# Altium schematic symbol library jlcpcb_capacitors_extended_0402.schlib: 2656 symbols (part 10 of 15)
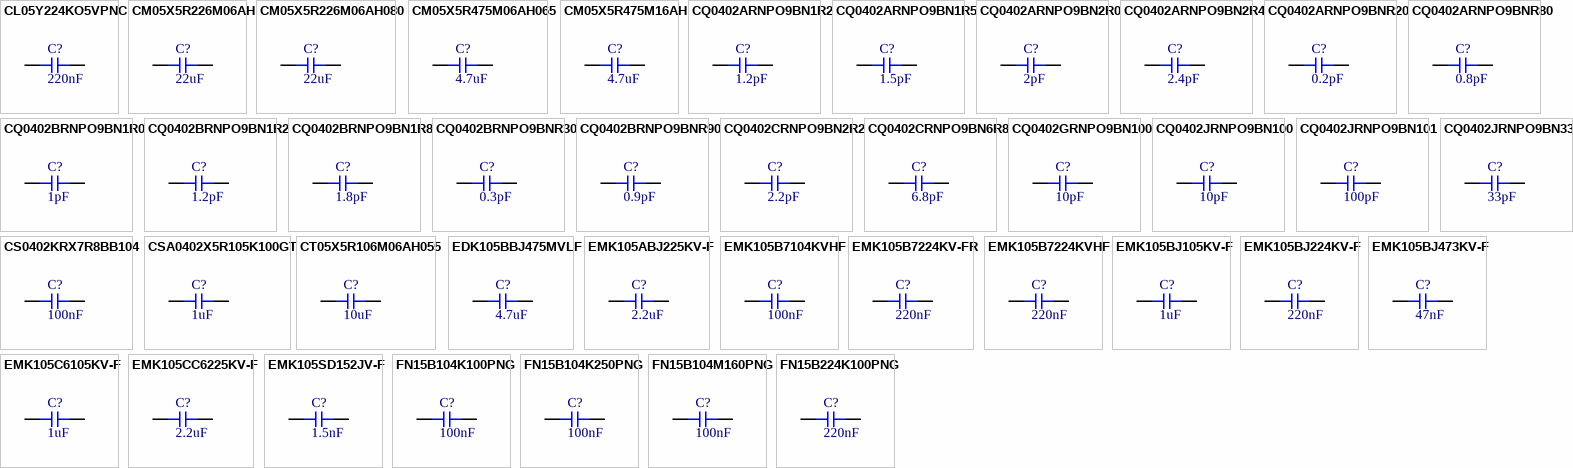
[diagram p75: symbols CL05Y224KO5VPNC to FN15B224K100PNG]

## CQ0402ARNPO9BN2R4
designator C?  Capacitance: 2.4pF  (hidden comment: *)
Capacitor, Ceramic (MLCC), 2.4pF, ±0.05pF, 50V, NP0, ±0.05pF, SMD 0402; Manufacturer: YAGEO; Manufacturer Part Number: CQ0402ARNPO9BN2R4
footprint CAP-0402 (0402 (1005M) Capacitor)
pins: 1, 2

## CQ0402ARNPO9BNR20
designator C?  Capacitance: 0.2pF  (hidden comment: *)
Capacitor, Ceramic (MLCC), 0.2pF, ±0.05pF, 50V, NP0, ±0.05pF, SMD 0402; Manufacturer: YAGEO; Manufacturer Part Number: CQ0402ARNPO9BNR20
footprint CAP-0402 (0402 (1005M) Capacitor)
pins: 1, 2

## CQ0402ARNPO9BNR80
designator C?  Capacitance: 0.8pF  (hidden comment: *)
Capacitor, Ceramic (MLCC), 0.8pF, ±0.05pF, 50V, NP0, ±0.05pF, SMD 0402; Manufacturer: YAGEO; Manufacturer Part Number: CQ0402ARNPO9BNR80
footprint CAP-0402 (0402 (1005M) Capacitor)
pins: 1, 2

## CQ0402BRNPO9BN1R0
designator C?  Capacitance: 1pF  (hidden comment: *)
Capacitor, Ceramic (MLCC), 1pF, ±0.1pF, 50V, NP0, ±0.1pF, SMD 0402; Manufacturer: YAGEO; Manufacturer Part Number: CQ0402BRNPO9BN1R0
footprint CAP-0402 (0402 (1005M) Capacitor)
pins: 1, 2

## CQ0402BRNPO9BN1R2
designator C?  Capacitance: 1.2pF  (hidden comment: *)
Capacitor, Ceramic (MLCC), 1.2pF, ±0.1pF, 50V, NP0, ±0.1pF, SMD 0402; Manufacturer: YAGEO; Manufacturer Part Number: CQ0402BRNPO9BN1R2
footprint CAP-0402 (0402 (1005M) Capacitor)
pins: 1, 2

## CQ0402BRNPO9BN1R8
designator C?  Capacitance: 1.8pF  (hidden comment: *)
Capacitor, Ceramic (MLCC), 1.8pF, ±0.1pF, 50V, NP0, ±0.1pF, SMD 0402; Manufacturer: YAGEO; Manufacturer Part Number: CQ0402BRNPO9BN1R8
footprint CAP-0402 (0402 (1005M) Capacitor)
pins: 1, 2

## CQ0402BRNPO9BNR30
designator C?  Capacitance: 0.3pF  (hidden comment: *)
Capacitor, Ceramic (MLCC), 0.3pF, ±0.1pF, 50V, NP0, ±0.1pF, SMD 0402; Manufacturer: YAGEO; Manufacturer Part Number: CQ0402BRNPO9BNR30
footprint CAP-0402 (0402 (1005M) Capacitor)
pins: 1, 2

## CQ0402BRNPO9BNR90
designator C?  Capacitance: 0.9pF  (hidden comment: *)
Capacitor, Ceramic (MLCC), 0.9pF, ±0.1pF, 50V, NP0, ±0.1pF, SMD 0402; Manufacturer: YAGEO; Manufacturer Part Number: CQ0402BRNPO9BNR90
footprint CAP-0402 (0402 (1005M) Capacitor)
pins: 1, 2

## CQ0402CRNPO9BN2R2
designator C?  Capacitance: 2.2pF  (hidden comment: *)
Capacitor, Ceramic (MLCC), 2.2pF, ±0.25pF, 50V, NP0, ±0.25pF, SMD 0402; Manufacturer: YAGEO; Manufacturer Part Number: CQ0402CRNPO9BN2R2
footprint CAP-0402 (0402 (1005M) Capacitor)
pins: 1, 2

## CQ0402CRNPO9BN6R8
designator C?  Capacitance: 6.8pF  (hidden comment: *)
Capacitor, Ceramic (MLCC), 6.8pF, ±0.25pF, 50V, NP0, ±0.25pF, SMD 0402; Manufacturer: YAGEO; Manufacturer Part Number: CQ0402CRNPO9BN6R8
footprint CAP-0402 (0402 (1005M) Capacitor)
pins: 1, 2

## CQ0402GRNPO9BN100
designator C?  Capacitance: 10pF  (hidden comment: *)
Capacitor, Ceramic (MLCC), 10pF, ±2%, 50V, NP0, ±2%, SMD 0402; Manufacturer: YAGEO; Manufacturer Part Number: CQ0402GRNPO9BN100
footprint CAP-0402 (0402 (1005M) Capacitor)
pins: 1, 2

## CQ0402JRNPO9BN100
designator C?  Capacitance: 10pF  (hidden comment: *)
Capacitor, Ceramic (MLCC), 10pF, ±5%, 50V, NP0, ±5%, SMD 0402; Manufacturer: YAGEO; Manufacturer Part Number: CQ0402JRNPO9BN100
footprint CAP-0402 (0402 (1005M) Capacitor)
pins: 1, 2

## CQ0402JRNPO9BN101
designator C?  Capacitance: 100pF  (hidden comment: *)
Capacitor, Ceramic (MLCC), 100pF, ±5%, 50V, NP0, ±5%, SMD 0402; Manufacturer: YAGEO; Manufacturer Part Number: CQ0402JRNPO9BN101
footprint CAP-0402 (0402 (1005M) Capacitor)
pins: 1, 2

## CQ0402JRNPO9BN330
designator C?  Capacitance: 33pF  (hidden comment: *)
Capacitor, Ceramic (MLCC), 33pF, ±5%, 50V, NP0, ±5%, SMD 0402; Manufacturer: YAGEO; Manufacturer Part Number: CQ0402JRNPO9BN330
footprint CAP-0402 (0402 (1005M) Capacitor)
pins: 1, 2

## CS0402KRX7R8BB104
designator C?  Capacitance: 100nF  (hidden comment: *)
Capacitor, Ceramic (MLCC), 100nF, ±10%, 25V, X7R, ±10%, SMD 0402; Manufacturer: YAGEO; Manufacturer Part Number: CS0402KRX7R8BB104
footprint CAP-0402 (0402 (1005M) Capacitor)
pins: 1, 2

## CSA0402X5R105K100GT
designator C?  Capacitance: 1uF  (hidden comment: *)
Capacitor, Ceramic (MLCC), 1uF, ±10%, 10V, X5R, ±10%, SMD 0402; Manufacturer: HRE; Manufacturer Part Number: CSA0402X5R105K100GT
footprint CAP-0402 (0402 (1005M) Capacitor)
pins: 1, 2

## CT05X5R106M06AH055
designator C?  Capacitance: 10uF  (hidden comment: *)
Capacitor, Ceramic (MLCC), 10uF, ±20%, 6.3V, X5R, ±20%, SMD 0402; Manufacturer: Kyocera; Manufacturer Part Number: CT05X5R106M06AH055
footprint CAP-0402 (0402 (1005M) Capacitor)
pins: 1, 2

## EDK105BBJ475MVLF
designator C?  Capacitance: 4.7uF  (hidden comment: *)
Capacitor, Ceramic (MLCC), 4.7uF, ±20%, 16V, ±20%, SMD 0402; Manufacturer: Taiyo Yuden; Manufacturer Part Number: EDK105BBJ475MVLF
footprint CAP-0402 (0402 (1005M) Capacitor)
pins: 1, 2

## EMK105ABJ225KV-F
designator C?  Capacitance: 2.2uF  (hidden comment: *)
Capacitor, Ceramic (MLCC), 2.2uF, ±10%, 16V, X5R, ±10%, SMD 0402; Manufacturer: Taiyo Yuden; Manufacturer Part Number: EMK105ABJ225KV-F
footprint CAP-0402 (0402 (1005M) Capacitor)
pins: 1, 2

## EMK105B7104KVHF
designator C?  Capacitance: 100nF  (hidden comment: *)
Capacitor, Ceramic (MLCC), 100nF, ±10%, 16V, X7R, ±10%, SMD 0402; Manufacturer: Taiyo Yuden; Manufacturer Part Number: EMK105B7104KVHF
footprint CAP-0402 (0402 (1005M) Capacitor)
pins: 1, 2

## EMK105B7224KV-FR
designator C?  Capacitance: 220nF  (hidden comment: *)
Capacitor, Ceramic (MLCC), 220nF, ±10%, 16V, X7R, ±10%, SMD 0402; Manufacturer: Taiyo Yuden; Manufacturer Part Number: EMK105B7224KV-FR
footprint CAP-0402 (0402 (1005M) Capacitor)
pins: 1, 2

## EMK105B7224KVHF
designator C?  Capacitance: 220nF  (hidden comment: *)
Capacitor, Ceramic (MLCC), 220nF, ±10%, 16V, X7R, ±10%, SMD 0402; Manufacturer: Taiyo Yuden; Manufacturer Part Number: EMK105B7224KVHF
footprint CAP-0402 (0402 (1005M) Capacitor)
pins: 1, 2

## EMK105BJ105KV-F
designator C?  Capacitance: 1uF  (hidden comment: *)
Capacitor, Ceramic (MLCC), 1uF, ±10%, 16V, X5R, ±10%, SMD 0402; Manufacturer: Taiyo Yuden; Manufacturer Part Number: EMK105BJ105KV-F
footprint CAP-0402 (0402 (1005M) Capacitor)
pins: 1, 2

## EMK105BJ224KV-F
designator C?  Capacitance: 220nF  (hidden comment: *)
Capacitor, Ceramic (MLCC), 220nF, ±10%, 16V, X5R, ±10%, SMD 0402; Manufacturer: Taiyo Yuden; Manufacturer Part Number: EMK105BJ224KV-F
footprint CAP-0402 (0402 (1005M) Capacitor)
pins: 1, 2

## EMK105BJ473KV-F
designator C?  Capacitance: 47nF  (hidden comment: *)
Capacitor, Ceramic (MLCC), 47nF, ±10%, 16V, X5R, ±10%, SMD 0402; Manufacturer: Taiyo Yuden; Manufacturer Part Number: EMK105BJ473KV-F
footprint CAP-0402 (0402 (1005M) Capacitor)
pins: 1, 2

## EMK105C6105KV-F
designator C?  Capacitance: 1uF  (hidden comment: *)
Capacitor, Ceramic (MLCC), 1uF, ±10%, 16V, ±10%, SMD 0402; Manufacturer: Taiyo Yuden; Manufacturer Part Number: EMK105C6105KV-F
footprint CAP-0402 (0402 (1005M) Capacitor)
pins: 1, 2

## EMK105CC6225KV-F
designator C?  Capacitance: 2.2uF  (hidden comment: *)
Capacitor, Ceramic (MLCC), 2.2uF, ±10%, ±10%, SMD 0402; Manufacturer: Taiyo Yuden; Manufacturer Part Number: EMK105CC6225KV-F
footprint CAP-0402 (0402 (1005M) Capacitor)
pins: 1, 2

## EMK105SD152JV-F
designator C?  Capacitance: 1.5nF  (hidden comment: *)
Capacitor, Ceramic (MLCC), 1.5nF, ±5%, 16V, ±5%, SMD 0402; Manufacturer: Taiyo Yuden; Manufacturer Part Number: EMK105SD152JV-F
footprint CAP-0402 (0402 (1005M) Capacitor)
pins: 1, 2

## FN15B104K100PNG
designator C?  Capacitance: 100nF  (hidden comment: *)
Capacitor, Ceramic (MLCC), 100nF, ±10%, 10V, X5R, ±10%, SMD 0402; Manufacturer: PSA(Prosperity Dielectrics); Manufacturer Part Number: FN15B104K100PNG
footprint CAP-0402 (0402 (1005M) Capacitor)
pins: 1, 2

## FN15B104K250PNG
designator C?  Capacitance: 100nF  (hidden comment: *)
Capacitor, Ceramic (MLCC), 100nF, ±10%, 25V, X5R, ±10%, SMD 0402; Manufacturer: PSA(Prosperity Dielectrics); Manufacturer Part Number: FN15B104K250PNG
footprint CAP-0402 (0402 (1005M) Capacitor)
pins: 1, 2

## FN15B104M160PNG
designator C?  Capacitance: 100nF  (hidden comment: *)
Capacitor, Ceramic (MLCC), 100nF, ±20%, 16V, X5R, ±20%, SMD 0402; Manufacturer: PSA(Prosperity Dielectrics); Manufacturer Part Number: FN15B104M160PNG
footprint CAP-0402 (0402 (1005M) Capacitor)
pins: 1, 2

## FN15B224K100PNG
designator C?  Capacitance: 220nF  (hidden comment: *)
Capacitor, Ceramic (MLCC), 220nF, ±10%, 10V, X5R, ±10%, SMD 0402; Manufacturer: PSA(Prosperity Dielectrics); Manufacturer Part Number: FN15B224K100PNG
footprint CAP-0402 (0402 (1005M) Capacitor)
pins: 1, 2

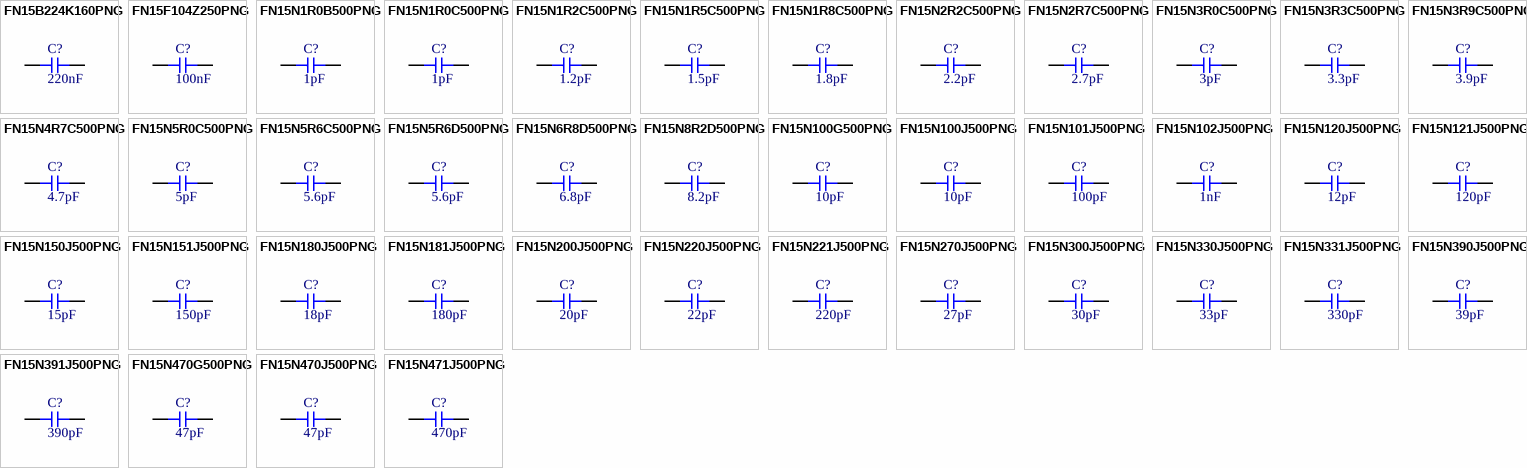
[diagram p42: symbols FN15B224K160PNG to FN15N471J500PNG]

## FN15B224K160PNG
designator C?  Capacitance: 220nF  (hidden comment: *)
Capacitor, Ceramic (MLCC), 220nF, ±10%, 16V, X5R, ±10%, SMD 0402; Manufacturer: PSA(Prosperity Dielectrics); Manufacturer Part Number: FN15B224K160PNG
footprint CAP-0402 (0402 (1005M) Capacitor)
pins: 1, 2

## FN15F104Z250PNG
designator C?  Capacitance: 100nF  (hidden comment: *)
Capacitor, Ceramic (MLCC), 100nF, 25V, Y5V, SMD 0402; Manufacturer: PSA(Prosperity Dielectrics); Manufacturer Part Number: FN15F104Z250PNG; Temperature Rating: -20%~+80%
footprint CAP-0402 (0402 (1005M) Capacitor)
pins: 1, 2

## FN15N1R0B500PNG
designator C?  Capacitance: 1pF  (hidden comment: *)
Capacitor, Ceramic (MLCC), 1pF, ±0.1pF, 50V, C0G, ±0.1pF, SMD 0402; Manufacturer: PSA(Prosperity Dielectrics); Manufacturer Part Number: FN15N1R0B500PNG
footprint CAP-0402 (0402 (1005M) Capacitor)
pins: 1, 2

## FN15N1R0C500PNG
designator C?  Capacitance: 1pF  (hidden comment: *)
Capacitor, Ceramic (MLCC), 1pF, ±0.25pF, 50V, C0G, ±0.25pF, SMD 0402; Manufacturer: PSA(Prosperity Dielectrics); Manufacturer Part Number: FN15N1R0C500PNG
footprint CAP-0402 (0402 (1005M) Capacitor)
pins: 1, 2

## FN15N1R2C500PNG
designator C?  Capacitance: 1.2pF  (hidden comment: *)
Capacitor, Ceramic (MLCC), 1.2pF, ±0.25pF, 50V, C0G, ±0.25pF, SMD 0402; Manufacturer: PSA(Prosperity Dielectrics); Manufacturer Part Number: FN15N1R2C500PNG
footprint CAP-0402 (0402 (1005M) Capacitor)
pins: 1, 2

## FN15N1R5C500PNG
designator C?  Capacitance: 1.5pF  (hidden comment: *)
Capacitor, Ceramic (MLCC), 1.5pF, ±0.25pF, 50V, C0G, ±0.25pF, SMD 0402; Manufacturer: PSA(Prosperity Dielectrics); Manufacturer Part Number: FN15N1R5C500PNG
footprint CAP-0402 (0402 (1005M) Capacitor)
pins: 1, 2

## FN15N1R8C500PNG
designator C?  Capacitance: 1.8pF  (hidden comment: *)
Capacitor, Ceramic (MLCC), 1.8pF, ±0.25pF, 50V, C0G, ±0.25pF, SMD 0402; Manufacturer: PSA(Prosperity Dielectrics); Manufacturer Part Number: FN15N1R8C500PNG
footprint CAP-0402 (0402 (1005M) Capacitor)
pins: 1, 2

## FN15N2R2C500PNG
designator C?  Capacitance: 2.2pF  (hidden comment: *)
Capacitor, Ceramic (MLCC), 2.2pF, ±0.25pF, 50V, C0G, ±0.25pF, SMD 0402; Manufacturer: PSA(Prosperity Dielectrics); Manufacturer Part Number: FN15N2R2C500PNG
footprint CAP-0402 (0402 (1005M) Capacitor)
pins: 1, 2

## FN15N2R7C500PNG
designator C?  Capacitance: 2.7pF  (hidden comment: *)
Capacitor, Ceramic (MLCC), 2.7pF, ±0.25pF, 50V, C0G, ±0.25pF, SMD 0402; Manufacturer: PSA(Prosperity Dielectrics); Manufacturer Part Number: FN15N2R7C500PNG
footprint CAP-0402 (0402 (1005M) Capacitor)
pins: 1, 2

## FN15N3R0C500PNG
designator C?  Capacitance: 3pF  (hidden comment: *)
Capacitor, Ceramic (MLCC), 3pF, ±0.25pF, 50V, C0G, ±0.25pF, SMD 0402; Manufacturer: PSA(Prosperity Dielectrics); Manufacturer Part Number: FN15N3R0C500PNG
footprint CAP-0402 (0402 (1005M) Capacitor)
pins: 1, 2

## FN15N3R3C500PNG
designator C?  Capacitance: 3.3pF  (hidden comment: *)
Capacitor, Ceramic (MLCC), 3.3pF, ±0.25pF, 50V, C0G, ±0.25pF, SMD 0402; Manufacturer: PSA(Prosperity Dielectrics); Manufacturer Part Number: FN15N3R3C500PNG
footprint CAP-0402 (0402 (1005M) Capacitor)
pins: 1, 2

## FN15N3R9C500PNG
designator C?  Capacitance: 3.9pF  (hidden comment: *)
Capacitor, Ceramic (MLCC), 3.9pF, ±0.25pF, 50V, C0G, ±0.25pF, SMD 0402; Manufacturer: PSA(Prosperity Dielectrics); Manufacturer Part Number: FN15N3R9C500PNG
footprint CAP-0402 (0402 (1005M) Capacitor)
pins: 1, 2

## FN15N4R7C500PNG
designator C?  Capacitance: 4.7pF  (hidden comment: *)
Capacitor, Ceramic (MLCC), 4.7pF, ±0.25pF, 50V, C0G, ±0.25pF, SMD 0402; Manufacturer: PSA(Prosperity Dielectrics); Manufacturer Part Number: FN15N4R7C500PNG
footprint CAP-0402 (0402 (1005M) Capacitor)
pins: 1, 2

## FN15N5R0C500PNG
designator C?  Capacitance: 5pF  (hidden comment: *)
Capacitor, Ceramic (MLCC), 5pF, ±0.25pF, 50V, C0G, ±0.25pF, SMD 0402; Manufacturer: PSA(Prosperity Dielectrics); Manufacturer Part Number: FN15N5R0C500PNG
footprint CAP-0402 (0402 (1005M) Capacitor)
pins: 1, 2

## FN15N5R6C500PNG
designator C?  Capacitance: 5.6pF  (hidden comment: *)
Capacitor, Ceramic (MLCC), 5.6pF, ±0.25pF, 50V, NP0, ±0.25pF, SMD 0402; Manufacturer: PSA(Prosperity Dielectrics); Manufacturer Part Number: FN15N5R6C500PNG
footprint CAP-0402 (0402 (1005M) Capacitor)
pins: 1, 2

## FN15N5R6D500PNG
designator C?  Capacitance: 5.6pF  (hidden comment: *)
Capacitor, Ceramic (MLCC), 5.6pF, ±0.5pF, 50V, C0G, ±0.5pF, SMD 0402; Manufacturer: PSA(Prosperity Dielectrics); Manufacturer Part Number: FN15N5R6D500PNG
footprint CAP-0402 (0402 (1005M) Capacitor)
pins: 1, 2

## FN15N6R8D500PNG
designator C?  Capacitance: 6.8pF  (hidden comment: *)
Capacitor, Ceramic (MLCC), 6.8pF, ±0.5pF, 50V, C0G, ±0.5pF, SMD 0402; Manufacturer: PSA(Prosperity Dielectrics); Manufacturer Part Number: FN15N6R8D500PNG
footprint CAP-0402 (0402 (1005M) Capacitor)
pins: 1, 2

## FN15N8R2D500PNG
designator C?  Capacitance: 8.2pF  (hidden comment: *)
Capacitor, Ceramic (MLCC), 8.2pF, ±0.5pF, 50V, C0G, ±0.5pF, SMD 0402; Manufacturer: PSA(Prosperity Dielectrics); Manufacturer Part Number: FN15N8R2D500PNG
footprint CAP-0402 (0402 (1005M) Capacitor)
pins: 1, 2

## FN15N100G500PNG
designator C?  Capacitance: 10pF  (hidden comment: *)
Capacitor, Ceramic (MLCC), 10pF, ±2%, 50V, C0G, ±2%, SMD 0402; Manufacturer: PSA(Prosperity Dielectrics); Manufacturer Part Number: FN15N100G500PNG
footprint CAP-0402 (0402 (1005M) Capacitor)
pins: 1, 2

## FN15N100J500PNG
designator C?  Capacitance: 10pF  (hidden comment: *)
Capacitor, Ceramic (MLCC), 10pF, ±5%, 50V, C0G, ±5%, SMD 0402; Manufacturer: PSA(Prosperity Dielectrics); Manufacturer Part Number: FN15N100J500PNG
footprint CAP-0402 (0402 (1005M) Capacitor)
pins: 1, 2

## FN15N101J500PNG
designator C?  Capacitance: 100pF  (hidden comment: *)
Capacitor, Ceramic (MLCC), 100pF, ±5%, 50V, C0G, ±5%, SMD 0402; Manufacturer: PSA(Prosperity Dielectrics); Manufacturer Part Number: FN15N101J500PNG
footprint CAP-0402 (0402 (1005M) Capacitor)
pins: 1, 2

## FN15N102J500PNG
designator C?  Capacitance: 1nF  (hidden comment: *)
Capacitor, Ceramic (MLCC), 1nF, ±5%, 50V, NP0, ±5%, SMD 0402; Manufacturer: PSA(Prosperity Dielectrics); Manufacturer Part Number: FN15N102J500PNG
footprint CAP-0402 (0402 (1005M) Capacitor)
pins: 1, 2

## FN15N120J500PNG
designator C?  Capacitance: 12pF  (hidden comment: *)
Capacitor, Ceramic (MLCC), 12pF, ±5%, 50V, C0G, ±5%, SMD 0402; Manufacturer: PSA(Prosperity Dielectrics); Manufacturer Part Number: FN15N120J500PNG
footprint CAP-0402 (0402 (1005M) Capacitor)
pins: 1, 2

## FN15N121J500PNG
designator C?  Capacitance: 120pF  (hidden comment: *)
Capacitor, Ceramic (MLCC), 120pF, ±5%, 50V, C0G, ±5%, SMD 0402; Manufacturer: PSA(Prosperity Dielectrics); Manufacturer Part Number: FN15N121J500PNG
footprint CAP-0402 (0402 (1005M) Capacitor)
pins: 1, 2

## FN15N150J500PNG
designator C?  Capacitance: 15pF  (hidden comment: *)
Capacitor, Ceramic (MLCC), 15pF, ±5%, 50V, C0G, ±5%, SMD 0402; Manufacturer: PSA(Prosperity Dielectrics); Manufacturer Part Number: FN15N150J500PNG
footprint CAP-0402 (0402 (1005M) Capacitor)
pins: 1, 2

## FN15N151J500PNG
designator C?  Capacitance: 150pF  (hidden comment: *)
Capacitor, Ceramic (MLCC), 150pF, ±5%, 50V, C0G, ±5%, SMD 0402; Manufacturer: PSA(Prosperity Dielectrics); Manufacturer Part Number: FN15N151J500PNG
footprint CAP-0402 (0402 (1005M) Capacitor)
pins: 1, 2

## FN15N180J500PNG
designator C?  Capacitance: 18pF  (hidden comment: *)
Capacitor, Ceramic (MLCC), 18pF, ±5%, 50V, C0G, ±5%, SMD 0402; Manufacturer: PSA(Prosperity Dielectrics); Manufacturer Part Number: FN15N180J500PNG
footprint CAP-0402 (0402 (1005M) Capacitor)
pins: 1, 2

## FN15N181J500PNG
designator C?  Capacitance: 180pF  (hidden comment: *)
Capacitor, Ceramic (MLCC), 180pF, ±5%, 50V, NP0, ±5%, SMD 0402; Manufacturer: PSA(Prosperity Dielectrics); Manufacturer Part Number: FN15N181J500PNG
footprint CAP-0402 (0402 (1005M) Capacitor)
pins: 1, 2

## FN15N200J500PNG
designator C?  Capacitance: 20pF  (hidden comment: *)
Capacitor, Ceramic (MLCC), 20pF, ±5%, 50V, C0G, ±5%, SMD 0402; Manufacturer: PSA(Prosperity Dielectrics); Manufacturer Part Number: FN15N200J500PNG
footprint CAP-0402 (0402 (1005M) Capacitor)
pins: 1, 2

## FN15N220J500PNG
designator C?  Capacitance: 22pF  (hidden comment: *)
Capacitor, Ceramic (MLCC), 22pF, ±5%, 50V, NP0, ±5%, SMD 0402; Manufacturer: PSA(Prosperity Dielectrics); Manufacturer Part Number: FN15N220J500PNG
footprint CAP-0402 (0402 (1005M) Capacitor)
pins: 1, 2

## FN15N221J500PNG
designator C?  Capacitance: 220pF  (hidden comment: *)
Capacitor, Ceramic (MLCC), 220pF, ±5%, 50V, C0G, ±5%, SMD 0402; Manufacturer: PSA(Prosperity Dielectrics); Manufacturer Part Number: FN15N221J500PNG
footprint CAP-0402 (0402 (1005M) Capacitor)
pins: 1, 2

## FN15N270J500PNG
designator C?  Capacitance: 27pF  (hidden comment: *)
Capacitor, Ceramic (MLCC), 27pF, ±5%, 50V, C0G, ±5%, SMD 0402; Manufacturer: PSA(Prosperity Dielectrics); Manufacturer Part Number: FN15N270J500PNG
footprint CAP-0402 (0402 (1005M) Capacitor)
pins: 1, 2

## FN15N300J500PNG
designator C?  Capacitance: 30pF  (hidden comment: *)
Capacitor, Ceramic (MLCC), 30pF, ±5%, 50V, NP0, ±5%, SMD 0402; Manufacturer: PSA(Prosperity Dielectrics); Manufacturer Part Number: FN15N300J500PNG
footprint CAP-0402 (0402 (1005M) Capacitor)
pins: 1, 2

## FN15N330J500PNG
designator C?  Capacitance: 33pF  (hidden comment: *)
Capacitor, Ceramic (MLCC), 33pF, ±5%, 50V, C0G, ±5%, SMD 0402; Manufacturer: PSA(Prosperity Dielectrics); Manufacturer Part Number: FN15N330J500PNG
footprint CAP-0402 (0402 (1005M) Capacitor)
pins: 1, 2

## FN15N331J500PNG
designator C?  Capacitance: 330pF  (hidden comment: *)
Capacitor, Ceramic (MLCC), 330pF, ±5%, 50V, C0G, ±5%, SMD 0402; Manufacturer: PSA(Prosperity Dielectrics); Manufacturer Part Number: FN15N331J500PNG
footprint CAP-0402 (0402 (1005M) Capacitor)
pins: 1, 2

## FN15N390J500PNG
designator C?  Capacitance: 39pF  (hidden comment: *)
Capacitor, Ceramic (MLCC), 39pF, ±5%, 50V, NP0, ±5%, SMD 0402; Manufacturer: PSA(Prosperity Dielectrics); Manufacturer Part Number: FN15N390J500PNG
footprint CAP-0402 (0402 (1005M) Capacitor)
pins: 1, 2

## FN15N391J500PNG
designator C?  Capacitance: 390pF  (hidden comment: *)
Capacitor, Ceramic (MLCC), 390pF, ±5%, 50V, C0G, ±5%, SMD 0402; Manufacturer: PSA(Prosperity Dielectrics); Manufacturer Part Number: FN15N391J500PNG
footprint CAP-0402 (0402 (1005M) Capacitor)
pins: 1, 2

## FN15N470G500PNG
designator C?  Capacitance: 47pF  (hidden comment: *)
Capacitor, Ceramic (MLCC), 47pF, ±2%, 50V, NP0, ±2%, SMD 0402; Manufacturer: PSA(Prosperity Dielectrics); Manufacturer Part Number: FN15N470G500PNG
footprint CAP-0402 (0402 (1005M) Capacitor)
pins: 1, 2

## FN15N470J500PNG
designator C?  Capacitance: 47pF  (hidden comment: *)
Capacitor, Ceramic (MLCC), 47pF, ±5%, 50V, C0G, ±5%, SMD 0402; Manufacturer: PSA(Prosperity Dielectrics); Manufacturer Part Number: FN15N470J500PNG
footprint CAP-0402 (0402 (1005M) Capacitor)
pins: 1, 2

## FN15N471J500PNG
designator C?  Capacitance: 470pF  (hidden comment: *)
Capacitor, Ceramic (MLCC), 470pF, ±5%, 50V, C0G, ±5%, SMD 0402; Manufacturer: PSA(Prosperity Dielectrics); Manufacturer Part Number: FN15N471J500PNG
footprint CAP-0402 (0402 (1005M) Capacitor)
pins: 1, 2

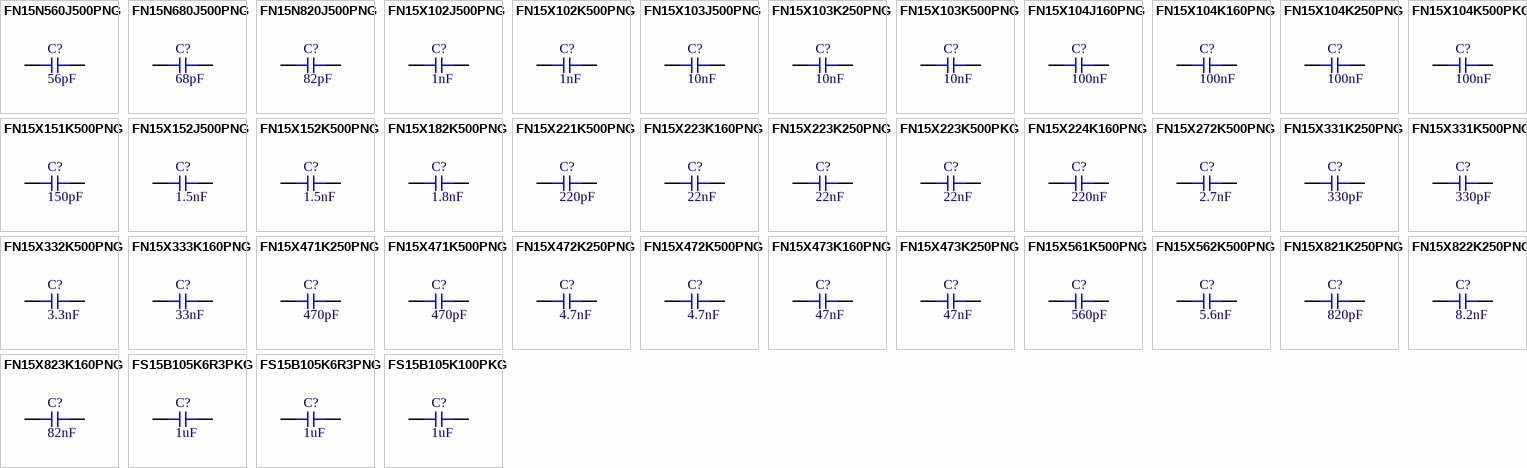
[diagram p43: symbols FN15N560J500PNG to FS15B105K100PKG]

## FN15N560J500PNG
designator C?  Capacitance: 56pF  (hidden comment: *)
Capacitor, Ceramic (MLCC), 56pF, ±5%, 50V, C0G, ±5%, SMD 0402; Manufacturer: PSA(Prosperity Dielectrics); Manufacturer Part Number: FN15N560J500PNG
footprint CAP-0402 (0402 (1005M) Capacitor)
pins: 1, 2

## FN15N680J500PNG
designator C?  Capacitance: 68pF  (hidden comment: *)
Capacitor, Ceramic (MLCC), 68pF, ±5%, 50V, C0G, ±5%, SMD 0402; Manufacturer: PSA(Prosperity Dielectrics); Manufacturer Part Number: FN15N680J500PNG
footprint CAP-0402 (0402 (1005M) Capacitor)
pins: 1, 2

## FN15N820J500PNG
designator C?  Capacitance: 82pF  (hidden comment: *)
Capacitor, Ceramic (MLCC), 82pF, ±5%, 50V, C0G, ±5%, SMD 0402; Manufacturer: PSA(Prosperity Dielectrics); Manufacturer Part Number: FN15N820J500PNG
footprint CAP-0402 (0402 (1005M) Capacitor)
pins: 1, 2

## FN15X102J500PNG
designator C?  Capacitance: 1nF  (hidden comment: *)
Capacitor, Ceramic (MLCC), 1nF, ±5%, 50V, X7R, ±5%, SMD 0402; Manufacturer: PSA(Prosperity Dielectrics); Manufacturer Part Number: FN15X102J500PNG
footprint CAP-0402 (0402 (1005M) Capacitor)
pins: 1, 2

## FN15X102K500PNG
designator C?  Capacitance: 1nF  (hidden comment: *)
Capacitor, Ceramic (MLCC), 1nF, ±10%, 50V, X7R, ±10%, SMD 0402; Manufacturer: PSA(Prosperity Dielectrics); Manufacturer Part Number: FN15X102K500PNG
footprint CAP-0402 (0402 (1005M) Capacitor)
pins: 1, 2

## FN15X103J500PNG
designator C?  Capacitance: 10nF  (hidden comment: *)
Capacitor, Ceramic (MLCC), 10nF, ±5%, 50V, X7R, ±5%, SMD 0402; Manufacturer: PSA(Prosperity Dielectrics); Manufacturer Part Number: FN15X103J500PNG
footprint CAP-0402 (0402 (1005M) Capacitor)
pins: 1, 2

## FN15X103K250PNG
designator C?  Capacitance: 10nF  (hidden comment: *)
Capacitor, Ceramic (MLCC), 10nF, ±10%, 25V, X7R, ±10%, SMD 0402; Manufacturer: PSA(Prosperity Dielectrics); Manufacturer Part Number: FN15X103K250PNG
footprint CAP-0402 (0402 (1005M) Capacitor)
pins: 1, 2

## FN15X103K500PNG
designator C?  Capacitance: 10nF  (hidden comment: *)
Capacitor, Ceramic (MLCC), 10nF, ±10%, 50V, X7R, ±10%, SMD 0402; Manufacturer: PSA(Prosperity Dielectrics); Manufacturer Part Number: FN15X103K500PNG
footprint CAP-0402 (0402 (1005M) Capacitor)
pins: 1, 2

## FN15X104J160PNG
designator C?  Capacitance: 100nF  (hidden comment: *)
Capacitor, Ceramic (MLCC), 100nF, ±5%, 16V, X7R, ±5%, SMD 0402; Manufacturer: PSA(Prosperity Dielectrics); Manufacturer Part Number: FN15X104J160PNG
footprint CAP-0402 (0402 (1005M) Capacitor)
pins: 1, 2

## FN15X104K160PNG
designator C?  Capacitance: 100nF  (hidden comment: *)
Capacitor, Ceramic (MLCC), 100nF, ±10%, 16V, X7R, ±10%, SMD 0402; Manufacturer: PSA(Prosperity Dielectrics); Manufacturer Part Number: FN15X104K160PNG
footprint CAP-0402 (0402 (1005M) Capacitor)
pins: 1, 2

## FN15X104K250PNG
designator C?  Capacitance: 100nF  (hidden comment: *)
Capacitor, Ceramic (MLCC), 100nF, ±10%, 25V, X7R, ±10%, SMD 0402; Manufacturer: PSA(Prosperity Dielectrics); Manufacturer Part Number: FN15X104K250PNG
footprint CAP-0402 (0402 (1005M) Capacitor)
pins: 1, 2

## FN15X104K500PKG
designator C?  Capacitance: 100nF  (hidden comment: *)
Capacitor, Ceramic (MLCC), 100nF, ±10%, 50V, X7R, ±10%, SMD 0402; Manufacturer: PSA(Prosperity Dielectrics); Manufacturer Part Number: FN15X104K500PKG
footprint CAP-0402 (0402 (1005M) Capacitor)
pins: 1, 2

## FN15X151K500PNG
designator C?  Capacitance: 150pF  (hidden comment: *)
Capacitor, Ceramic (MLCC), 150pF, ±10%, 50V, X7R, ±10%, SMD 0402; Manufacturer: PSA(Prosperity Dielectrics); Manufacturer Part Number: FN15X151K500PNG
footprint CAP-0402 (0402 (1005M) Capacitor)
pins: 1, 2

## FN15X152J500PNG
designator C?  Capacitance: 1.5nF  (hidden comment: *)
Capacitor, Ceramic (MLCC), 1.5nF, ±5%, 50V, X7R, ±5%, SMD 0402; Manufacturer: PSA(Prosperity Dielectrics); Manufacturer Part Number: FN15X152J500PNG
footprint CAP-0402 (0402 (1005M) Capacitor)
pins: 1, 2

## FN15X152K500PNG
designator C?  Capacitance: 1.5nF  (hidden comment: *)
Capacitor, Ceramic (MLCC), 1.5nF, ±10%, 50V, X7R, ±10%, SMD 0402; Manufacturer: PSA(Prosperity Dielectrics); Manufacturer Part Number: FN15X152K500PNG
footprint CAP-0402 (0402 (1005M) Capacitor)
pins: 1, 2

## FN15X182K500PNG
designator C?  Capacitance: 1.8nF  (hidden comment: *)
Capacitor, Ceramic (MLCC), 1.8nF, ±10%, 50V, X7R, ±10%, SMD 0402; Manufacturer: PSA(Prosperity Dielectrics); Manufacturer Part Number: FN15X182K500PNG
footprint CAP-0402 (0402 (1005M) Capacitor)
pins: 1, 2

## FN15X221K500PNG
designator C?  Capacitance: 220pF  (hidden comment: *)
Capacitor, Ceramic (MLCC), 220pF, ±10%, 50V, X7R, ±10%, SMD 0402; Manufacturer: PSA(Prosperity Dielectrics); Manufacturer Part Number: FN15X221K500PNG
footprint CAP-0402 (0402 (1005M) Capacitor)
pins: 1, 2

## FN15X223K160PNG
designator C?  Capacitance: 22nF  (hidden comment: *)
Capacitor, Ceramic (MLCC), 22nF, ±10%, 16V, X7R, ±10%, SMD 0402; Manufacturer: PSA(Prosperity Dielectrics); Manufacturer Part Number: FN15X223K160PNG
footprint CAP-0402 (0402 (1005M) Capacitor)
pins: 1, 2

## FN15X223K250PNG
designator C?  Capacitance: 22nF  (hidden comment: *)
Capacitor, Ceramic (MLCC), 22nF, ±10%, 25V, X7R, ±10%, SMD 0402; Manufacturer: PSA(Prosperity Dielectrics); Manufacturer Part Number: FN15X223K250PNG
footprint CAP-0402 (0402 (1005M) Capacitor)
pins: 1, 2

## FN15X223K500PKG
designator C?  Capacitance: 22nF  (hidden comment: *)
Capacitor, Ceramic (MLCC), 22nF, ±10%, 50V, X7R, ±10%, SMD 0402; Manufacturer: PSA(Prosperity Dielectrics); Manufacturer Part Number: FN15X223K500PKG
footprint CAP-0402 (0402 (1005M) Capacitor)
pins: 1, 2

## FN15X224K160PNG
designator C?  Capacitance: 220nF  (hidden comment: *)
Capacitor, Ceramic (MLCC), 220nF, ±10%, 16V, X7R, ±10%, SMD 0402; Manufacturer: PSA(Prosperity Dielectrics); Manufacturer Part Number: FN15X224K160PNG
footprint CAP-0402 (0402 (1005M) Capacitor)
pins: 1, 2

## FN15X272K500PNG
designator C?  Capacitance: 2.7nF  (hidden comment: *)
Capacitor, Ceramic (MLCC), 2.7nF, ±10%, 50V, X7R, ±10%, SMD 0402; Manufacturer: PSA(Prosperity Dielectrics); Manufacturer Part Number: FN15X272K500PNG
footprint CAP-0402 (0402 (1005M) Capacitor)
pins: 1, 2

## FN15X331K250PNG
designator C?  Capacitance: 330pF  (hidden comment: *)
Capacitor, Ceramic (MLCC), 330pF, ±10%, 25V, ±10%, SMD 0402; Manufacturer: PSA(Prosperity Dielectrics); Manufacturer Part Number: FN15X331K250PNG
footprint CAP-0402 (0402 (1005M) Capacitor)
pins: 1, 2

## FN15X331K500PNG
designator C?  Capacitance: 330pF  (hidden comment: *)
Capacitor, Ceramic (MLCC), 330pF, ±10%, 50V, X7R, ±10%, SMD 0402; Manufacturer: PSA(Prosperity Dielectrics); Manufacturer Part Number: FN15X331K500PNG
footprint CAP-0402 (0402 (1005M) Capacitor)
pins: 1, 2

## FN15X332K500PNG
designator C?  Capacitance: 3.3nF  (hidden comment: *)
Capacitor, Ceramic (MLCC), 3.3nF, ±10%, 50V, X7R, ±10%, SMD 0402; Manufacturer: PSA(Prosperity Dielectrics); Manufacturer Part Number: FN15X332K500PNG
footprint CAP-0402 (0402 (1005M) Capacitor)
pins: 1, 2

## FN15X333K160PNG
designator C?  Capacitance: 33nF  (hidden comment: *)
Capacitor, Ceramic (MLCC), 33nF, ±10%, 16V, X7R, ±10%, SMD 0402; Manufacturer: PSA(Prosperity Dielectrics); Manufacturer Part Number: FN15X333K160PNG
footprint CAP-0402 (0402 (1005M) Capacitor)
pins: 1, 2

## FN15X471K250PNG
designator C?  Capacitance: 470pF  (hidden comment: *)
Capacitor, Ceramic (MLCC), 470pF, ±10%, 25V, ±10%, SMD 0402; Manufacturer: PSA(Prosperity Dielectrics); Manufacturer Part Number: FN15X471K250PNG
footprint CAP-0402 (0402 (1005M) Capacitor)
pins: 1, 2

## FN15X471K500PNG
designator C?  Capacitance: 470pF  (hidden comment: *)
Capacitor, Ceramic (MLCC), 470pF, ±10%, 50V, X7R, ±10%, SMD 0402; Manufacturer: PSA(Prosperity Dielectrics); Manufacturer Part Number: FN15X471K500PNG
footprint CAP-0402 (0402 (1005M) Capacitor)
pins: 1, 2

## FN15X472K250PNG
designator C?  Capacitance: 4.7nF  (hidden comment: *)
Capacitor, Ceramic (MLCC), 4.7nF, ±10%, 25V, X7R, ±10%, SMD 0402; Manufacturer: PSA(Prosperity Dielectrics); Manufacturer Part Number: FN15X472K250PNG
footprint CAP-0402 (0402 (1005M) Capacitor)
pins: 1, 2

## FN15X472K500PNG
designator C?  Capacitance: 4.7nF  (hidden comment: *)
Capacitor, Ceramic (MLCC), 4.7nF, ±10%, 50V, X7R, ±10%, SMD 0402; Manufacturer: PSA(Prosperity Dielectrics); Manufacturer Part Number: FN15X472K500PNG
footprint CAP-0402 (0402 (1005M) Capacitor)
pins: 1, 2

## FN15X473K160PNG
designator C?  Capacitance: 47nF  (hidden comment: *)
Capacitor, Ceramic (MLCC), 47nF, ±10%, 16V, X7R, ±10%, SMD 0402; Manufacturer: PSA(Prosperity Dielectrics); Manufacturer Part Number: FN15X473K160PNG
footprint CAP-0402 (0402 (1005M) Capacitor)
pins: 1, 2

## FN15X473K250PNG
designator C?  Capacitance: 47nF  (hidden comment: *)
Capacitor, Ceramic (MLCC), 47nF, ±10%, 25V, X7R, ±10%, SMD 0402; Manufacturer: PSA(Prosperity Dielectrics); Manufacturer Part Number: FN15X473K250PNG
footprint CAP-0402 (0402 (1005M) Capacitor)
pins: 1, 2

## FN15X561K500PNG
designator C?  Capacitance: 560pF  (hidden comment: *)
Capacitor, Ceramic (MLCC), 560pF, ±10%, 50V, X7R, ±10%, SMD 0402; Manufacturer: PSA(Prosperity Dielectrics); Manufacturer Part Number: FN15X561K500PNG
footprint CAP-0402 (0402 (1005M) Capacitor)
pins: 1, 2

## FN15X562K500PNG
designator C?  Capacitance: 5.6nF  (hidden comment: *)
Capacitor, Ceramic (MLCC), 5.6nF, ±10%, 50V, X7R, ±10%, SMD 0402; Manufacturer: PSA(Prosperity Dielectrics); Manufacturer Part Number: FN15X562K500PNG
footprint CAP-0402 (0402 (1005M) Capacitor)
pins: 1, 2

## FN15X821K250PNG
designator C?  Capacitance: 820pF  (hidden comment: *)
Capacitor, Ceramic (MLCC), 820pF, ±10%, 25V, X7R, ±10%, SMD 0402; Manufacturer: PSA(Prosperity Dielectrics); Manufacturer Part Number: FN15X821K250PNG
footprint CAP-0402 (0402 (1005M) Capacitor)
pins: 1, 2

## FN15X822K250PNG
designator C?  Capacitance: 8.2nF  (hidden comment: *)
Capacitor, Ceramic (MLCC), 8.2nF, ±10%, 25V, X7R, ±10%, SMD 0402; Manufacturer: PSA(Prosperity Dielectrics); Manufacturer Part Number: FN15X822K250PNG
footprint CAP-0402 (0402 (1005M) Capacitor)
pins: 1, 2

## FN15X823K160PNG
designator C?  Capacitance: 82nF  (hidden comment: *)
Capacitor, Ceramic (MLCC), 82nF, ±10%, 16V, X7R, ±10%, SMD 0402; Manufacturer: PSA(Prosperity Dielectrics); Manufacturer Part Number: FN15X823K160PNG
footprint CAP-0402 (0402 (1005M) Capacitor)
pins: 1, 2

## FS15B105K6R3PKG
designator C?  Capacitance: 1uF  (hidden comment: *)
Capacitor, Ceramic (MLCC), 1uF, ±10%, 6.3V, X5R, ±10%, SMD 0402; Manufacturer: PSA(Prosperity Dielectrics); Manufacturer Part Number: FS15B105K6R3PKG
footprint CAP-0402 (0402 (1005M) Capacitor)
pins: 1, 2

## FS15B105K6R3PNG
designator C?  Capacitance: 1uF  (hidden comment: *)
Capacitor, Ceramic (MLCC), 1uF, ±10%, 6.3V, X5R, ±10%, SMD 0402; Manufacturer: PSA(Prosperity Dielectrics); Manufacturer Part Number: FS15B105K6R3PNG
footprint CAP-0402 (0402 (1005M) Capacitor)
pins: 1, 2

## FS15B105K100PKG
designator C?  Capacitance: 1uF  (hidden comment: *)
Capacitor, Ceramic (MLCC), 1uF, ±10%, 10V, X5R, ±10%, SMD 0402; Manufacturer: PSA(Prosperity Dielectrics); Manufacturer Part Number: FS15B105K100PKG
footprint CAP-0402 (0402 (1005M) Capacitor)
pins: 1, 2

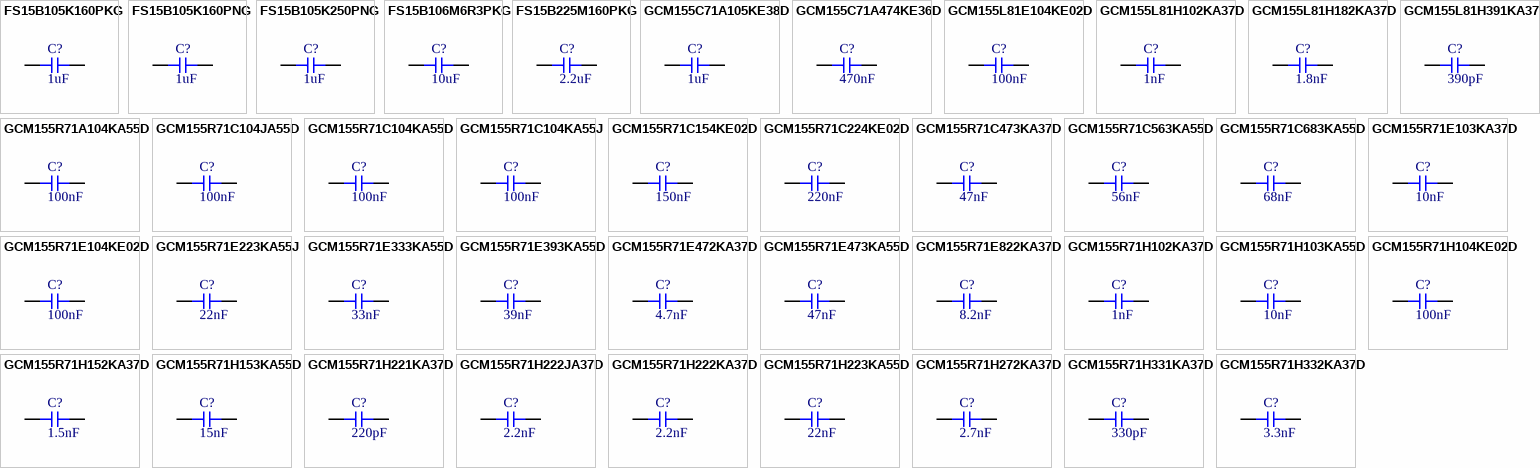
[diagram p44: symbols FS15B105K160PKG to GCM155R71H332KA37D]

## FS15B105K160PKG
designator C?  Capacitance: 1uF  (hidden comment: *)
Capacitor, Ceramic (MLCC), 1uF, ±10%, 16V, X5R, ±10%, SMD 0402; Manufacturer: PSA(Prosperity Dielectrics); Manufacturer Part Number: FS15B105K160PKG
footprint CAP-0402 (0402 (1005M) Capacitor)
pins: 1, 2

## FS15B105K160PNG
designator C?  Capacitance: 1uF  (hidden comment: *)
Capacitor, Ceramic (MLCC), 1uF, ±10%, 16V, X5R, ±10%, SMD 0402; Manufacturer: PSA(Prosperity Dielectrics); Manufacturer Part Number: FS15B105K160PNG
footprint CAP-0402 (0402 (1005M) Capacitor)
pins: 1, 2

## FS15B105K250PNG
designator C?  Capacitance: 1uF  (hidden comment: *)
Capacitor, Ceramic (MLCC), 1uF, ±10%, 25V, X5R, ±10%, SMD 0402; Manufacturer: PSA(Prosperity Dielectrics); Manufacturer Part Number: FS15B105K250PNG
footprint CAP-0402 (0402 (1005M) Capacitor)
pins: 1, 2

## FS15B106M6R3PKG
designator C?  Capacitance: 10uF  (hidden comment: *)
Capacitor, Ceramic (MLCC), 10uF, ±20%, 6.3V, X5R, ±20%, SMD 0402; Manufacturer: PSA(Prosperity Dielectrics); Manufacturer Part Number: FS15B106M6R3PKG
footprint CAP-0402 (0402 (1005M) Capacitor)
pins: 1, 2

## FS15B225M160PKG
designator C?  Capacitance: 2.2uF  (hidden comment: *)
Capacitor, Ceramic (MLCC), 2.2uF, ±20%, 16V, X5R, ±20%, SMD 0402; Manufacturer: PSA(Prosperity Dielectrics); Manufacturer Part Number: FS15B225M160PKG
footprint CAP-0402 (0402 (1005M) Capacitor)
pins: 1, 2

## GCM155C71A105KE38D
designator C?  Capacitance: 1uF  (hidden comment: *)
Capacitor, Ceramic (MLCC), 1uF, ±10%, 10V, X7S, ±10%, SMD 0402; Manufacturer: Murata Electronics; Manufacturer Part Number: GCM155C71A105KE38D
footprint CAP-0402 (0402 (1005M) Capacitor)
pins: 1, 2

## GCM155C71A474KE36D
designator C?  Capacitance: 470nF  (hidden comment: *)
Capacitor, Ceramic (MLCC), 470nF, ±10%, 10V, X7S, ±10%, SMD 0402; Manufacturer: Murata Electronics; Manufacturer Part Number: GCM155C71A474KE36D
footprint CAP-0402 (0402 (1005M) Capacitor)
pins: 1, 2

## GCM155L81E104KE02D
designator C?  Capacitance: 100nF  (hidden comment: *)
Capacitor, Ceramic (MLCC), 100nF, ±10%, 25V, ±10%, SMD 0402; Manufacturer: Murata Electronics; Manufacturer Part Number: GCM155L81E104KE02D
footprint CAP-0402 (0402 (1005M) Capacitor)
pins: 1, 2

## GCM155L81H102KA37D
designator C?  Capacitance: 1nF  (hidden comment: *)
Capacitor, Ceramic (MLCC), 1nF, ±10%, ±10%, SMD 0402; Manufacturer: Murata Electronics; Manufacturer Part Number: GCM155L81H102KA37D
footprint CAP-0402 (0402 (1005M) Capacitor)
pins: 1, 2

## GCM155L81H182KA37D
designator C?  Capacitance: 1.8nF  (hidden comment: *)
Capacitor, Ceramic (MLCC), 1.8nF, ±10%, ±10%, SMD 0402; Manufacturer: Murata Electronics; Manufacturer Part Number: GCM155L81H182KA37D
footprint CAP-0402 (0402 (1005M) Capacitor)
pins: 1, 2

## GCM155L81H391KA37D
designator C?  Capacitance: 390pF  (hidden comment: *)
Capacitor, Ceramic (MLCC), 390pF, ±10%, ±10%, SMD 0402; Manufacturer: Murata Electronics; Manufacturer Part Number: GCM155L81H391KA37D
footprint CAP-0402 (0402 (1005M) Capacitor)
pins: 1, 2

## GCM155R71A104KA55D
designator C?  Capacitance: 100nF  (hidden comment: *)
Capacitor, Ceramic (MLCC), 100nF, ±10%, 10V, X7R, ±10%, SMD 0402; Manufacturer: Murata Electronics; Manufacturer Part Number: GCM155R71A104KA55D
footprint CAP-0402 (0402 (1005M) Capacitor)
pins: 1, 2

## GCM155R71C104JA55D
designator C?  Capacitance: 100nF  (hidden comment: *)
Capacitor, Ceramic (MLCC), 100nF, ±5%, 16V, ±5%, SMD 0402; Manufacturer: Murata Electronics; Manufacturer Part Number: GCM155R71C104JA55D
footprint CAP-0402 (0402 (1005M) Capacitor)
pins: 1, 2

## GCM155R71C104KA55D
designator C?  Capacitance: 100nF  (hidden comment: *)
Capacitor, Ceramic (MLCC), 100nF, ±10%, 16V, X7R, ±10%, SMD 0402; Manufacturer: Murata Electronics; Manufacturer Part Number: GCM155R71C104KA55D
footprint CAP-0402 (0402 (1005M) Capacitor)
pins: 1, 2

## GCM155R71C104KA55J
designator C?  Capacitance: 100nF  (hidden comment: *)
Capacitor, Ceramic (MLCC), 100nF, ±10%, ±10%, SMD 0402; Manufacturer: Murata Electronics; Manufacturer Part Number: GCM155R71C104KA55J
footprint CAP-0402 (0402 (1005M) Capacitor)
pins: 1, 2

## GCM155R71C154KE02D
designator C?  Capacitance: 150nF  (hidden comment: *)
Capacitor, Ceramic (MLCC), 150nF, ±10%, 16V, X7R, ±10%, SMD 0402; Manufacturer: Murata Electronics; Manufacturer Part Number: GCM155R71C154KE02D
footprint CAP-0402 (0402 (1005M) Capacitor)
pins: 1, 2

## GCM155R71C224KE02D
designator C?  Capacitance: 220nF  (hidden comment: *)
Capacitor, Ceramic (MLCC), 220nF, ±10%, 16V, X7R, ±10%, SMD 0402; Manufacturer: Murata Electronics; Manufacturer Part Number: GCM155R71C224KE02D
footprint CAP-0402 (0402 (1005M) Capacitor)
pins: 1, 2

## GCM155R71C473KA37D
designator C?  Capacitance: 47nF  (hidden comment: *)
Capacitor, Ceramic (MLCC), 47nF, ±10%, 16V, X7R, ±10%, SMD 0402; Manufacturer: Murata Electronics; Manufacturer Part Number: GCM155R71C473KA37D
footprint CAP-0402 (0402 (1005M) Capacitor)
pins: 1, 2

## GCM155R71C563KA55D
designator C?  Capacitance: 56nF  (hidden comment: *)
Capacitor, Ceramic (MLCC), 56nF, ±10%, 16V, X7R, ±10%, SMD 0402; Manufacturer: Murata Electronics; Manufacturer Part Number: GCM155R71C563KA55D
footprint CAP-0402 (0402 (1005M) Capacitor)
pins: 1, 2

## GCM155R71C683KA55D
designator C?  Capacitance: 68nF  (hidden comment: *)
Capacitor, Ceramic (MLCC), 68nF, ±10%, 16V, X7R, ±10%, SMD 0402; Manufacturer: Murata Electronics; Manufacturer Part Number: GCM155R71C683KA55D
footprint CAP-0402 (0402 (1005M) Capacitor)
pins: 1, 2

## GCM155R71E103KA37D
designator C?  Capacitance: 10nF  (hidden comment: *)
Capacitor, Ceramic (MLCC), 10nF, ±10%, 25V, X7R, ±10%, SMD 0402; Manufacturer: Murata Electronics; Manufacturer Part Number: GCM155R71E103KA37D
footprint CAP-0402 (0402 (1005M) Capacitor)
pins: 1, 2

## GCM155R71E104KE02D
designator C?  Capacitance: 100nF  (hidden comment: *)
Capacitor, Ceramic (MLCC), 100nF, ±10%, 25V, X7R, ±10%, SMD 0402; Manufacturer: Murata Electronics; Manufacturer Part Number: GCM155R71E104KE02D
footprint CAP-0402 (0402 (1005M) Capacitor)
pins: 1, 2

## GCM155R71E223KA55J
designator C?  Capacitance: 22nF  (hidden comment: *)
Capacitor, Ceramic (MLCC), 22nF, ±10%, 25V, X7R, ±10%, SMD 0402; Manufacturer: Murata Electronics; Manufacturer Part Number: GCM155R71E223KA55J
footprint CAP-0402 (0402 (1005M) Capacitor)
pins: 1, 2

## GCM155R71E333KA55D
designator C?  Capacitance: 33nF  (hidden comment: *)
Capacitor, Ceramic (MLCC), 33nF, ±10%, 25V, X7R, ±10%, SMD 0402; Manufacturer: Murata Electronics; Manufacturer Part Number: GCM155R71E333KA55D
footprint CAP-0402 (0402 (1005M) Capacitor)
pins: 1, 2

## GCM155R71E393KA55D
designator C?  Capacitance: 39nF  (hidden comment: *)
Capacitor, Ceramic (MLCC), 39nF, ±10%, 25V, X7R, ±10%, SMD 0402; Manufacturer: Murata Electronics; Manufacturer Part Number: GCM155R71E393KA55D
footprint CAP-0402 (0402 (1005M) Capacitor)
pins: 1, 2

## GCM155R71E472KA37D
designator C?  Capacitance: 4.7nF  (hidden comment: *)
Capacitor, Ceramic (MLCC), 4.7nF, ±10%, ±10%, SMD 0402; Manufacturer: Murata Electronics; Manufacturer Part Number: GCM155R71E472KA37D
footprint CAP-0402 (0402 (1005M) Capacitor)
pins: 1, 2

## GCM155R71E473KA55D
designator C?  Capacitance: 47nF  (hidden comment: *)
Capacitor, Ceramic (MLCC), 47nF, ±10%, 25V, X7R, ±10%, SMD 0402; Manufacturer: Murata Electronics; Manufacturer Part Number: GCM155R71E473KA55D
footprint CAP-0402 (0402 (1005M) Capacitor)
pins: 1, 2

## GCM155R71E822KA37D
designator C?  Capacitance: 8.2nF  (hidden comment: *)
Capacitor, Ceramic (MLCC), 8.2nF, ±10%, 25V, X7R, ±10%, SMD 0402; Manufacturer: Murata Electronics; Manufacturer Part Number: GCM155R71E822KA37D
footprint CAP-0402 (0402 (1005M) Capacitor)
pins: 1, 2

## GCM155R71H102KA37D
designator C?  Capacitance: 1nF  (hidden comment: *)
Capacitor, Ceramic (MLCC), 1nF, ±10%, 50V, X7R, ±10%, SMD 0402; Manufacturer: Murata Electronics; Manufacturer Part Number: GCM155R71H102KA37D
footprint CAP-0402 (0402 (1005M) Capacitor)
pins: 1, 2

## GCM155R71H103KA55D
designator C?  Capacitance: 10nF  (hidden comment: *)
Capacitor, Ceramic (MLCC), 10nF, ±10%, 50V, X7R, ±10%, SMD 0402; Manufacturer: Murata Electronics; Manufacturer Part Number: GCM155R71H103KA55D
footprint CAP-0402 (0402 (1005M) Capacitor)
pins: 1, 2

## GCM155R71H104KE02D
designator C?  Capacitance: 100nF  (hidden comment: *)
Capacitor, Ceramic (MLCC), 100nF, ±10%, 50V, X7R, ±10%, SMD 0402; Manufacturer: Murata Electronics; Manufacturer Part Number: GCM155R71H104KE02D
footprint CAP-0402 (0402 (1005M) Capacitor)
pins: 1, 2

## GCM155R71H152KA37D
designator C?  Capacitance: 1.5nF  (hidden comment: *)
Capacitor, Ceramic (MLCC), 1.5nF, ±10%, 50V, X7R, ±10%, SMD 0402; Manufacturer: Murata Electronics; Manufacturer Part Number: GCM155R71H152KA37D
footprint CAP-0402 (0402 (1005M) Capacitor)
pins: 1, 2

## GCM155R71H153KA55D
designator C?  Capacitance: 15nF  (hidden comment: *)
Capacitor, Ceramic (MLCC), 15nF, ±10%, 50V, X7R, ±10%, SMD 0402; Manufacturer: Murata Electronics; Manufacturer Part Number: GCM155R71H153KA55D
footprint CAP-0402 (0402 (1005M) Capacitor)
pins: 1, 2

## GCM155R71H221KA37D
designator C?  Capacitance: 220pF  (hidden comment: *)
Capacitor, Ceramic (MLCC), 220pF, ±10%, 50V, X7R, ±10%, SMD 0402; Manufacturer: Murata Electronics; Manufacturer Part Number: GCM155R71H221KA37D
footprint CAP-0402 (0402 (1005M) Capacitor)
pins: 1, 2

## GCM155R71H222JA37D
designator C?  Capacitance: 2.2nF  (hidden comment: *)
Capacitor, Ceramic (MLCC), 2.2nF, ±5%, 50V, X7R, ±5%, SMD 0402; Manufacturer: Murata Electronics; Manufacturer Part Number: GCM155R71H222JA37D
footprint CAP-0402 (0402 (1005M) Capacitor)
pins: 1, 2

## GCM155R71H222KA37D
designator C?  Capacitance: 2.2nF  (hidden comment: *)
Capacitor, Ceramic (MLCC), 2.2nF, ±10%, 50V, X7R, ±10%, SMD 0402; Manufacturer: Murata Electronics; Manufacturer Part Number: GCM155R71H222KA37D
footprint CAP-0402 (0402 (1005M) Capacitor)
pins: 1, 2

## GCM155R71H223KA55D
designator C?  Capacitance: 22nF  (hidden comment: *)
Capacitor, Ceramic (MLCC), 22nF, ±10%, 50V, X7R, ±10%, SMD 0402; Manufacturer: Murata Electronics; Manufacturer Part Number: GCM155R71H223KA55D
footprint CAP-0402 (0402 (1005M) Capacitor)
pins: 1, 2

## GCM155R71H272KA37D
designator C?  Capacitance: 2.7nF  (hidden comment: *)
Capacitor, Ceramic (MLCC), 2.7nF, ±10%, 50V, X7R, ±10%, SMD 0402; Manufacturer: Murata Electronics; Manufacturer Part Number: GCM155R71H272KA37D
footprint CAP-0402 (0402 (1005M) Capacitor)
pins: 1, 2

## GCM155R71H331KA37D
designator C?  Capacitance: 330pF  (hidden comment: *)
Capacitor, Ceramic (MLCC), 330pF, ±10%, 50V, X7R, ±10%, SMD 0402; Manufacturer: Murata Electronics; Manufacturer Part Number: GCM155R71H331KA37D
footprint CAP-0402 (0402 (1005M) Capacitor)
pins: 1, 2

## GCM155R71H332KA37D
designator C?  Capacitance: 3.3nF  (hidden comment: *)
Capacitor, Ceramic (MLCC), 3.3nF, ±10%, 50V, X7R, ±10%, SMD 0402; Manufacturer: Murata Electronics; Manufacturer Part Number: GCM155R71H332KA37D
footprint CAP-0402 (0402 (1005M) Capacitor)
pins: 1, 2

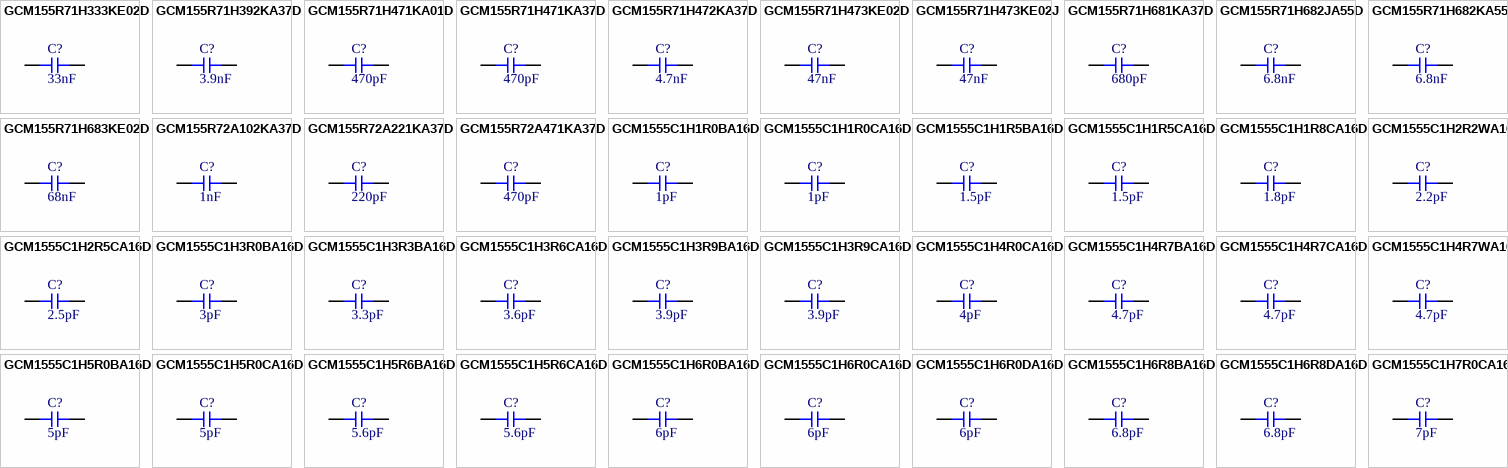
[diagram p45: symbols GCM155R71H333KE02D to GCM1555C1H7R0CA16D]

## GCM155R71H333KE02D
designator C?  Capacitance: 33nF  (hidden comment: *)
Capacitor, Ceramic (MLCC), 33nF, ±10%, 50V, X7R, ±10%, SMD 0402; Manufacturer: Murata Electronics; Manufacturer Part Number: GCM155R71H333KE02D
footprint CAP-0402 (0402 (1005M) Capacitor)
pins: 1, 2

## GCM155R71H392KA37D
designator C?  Capacitance: 3.9nF  (hidden comment: *)
Capacitor, Ceramic (MLCC), 3.9nF, ±10%, 50V, X7R, ±10%, SMD 0402; Manufacturer: Murata Electronics; Manufacturer Part Number: GCM155R71H392KA37D
footprint CAP-0402 (0402 (1005M) Capacitor)
pins: 1, 2

## GCM155R71H471KA01D
designator C?  Capacitance: 470pF  (hidden comment: *)
Capacitor, Ceramic (MLCC), 470pF, ±10%, 50V, X7R, ±10%, SMD 0402; Manufacturer: Murata Electronics; Manufacturer Part Number: GCM155R71H471KA01D
footprint CAP-0402 (0402 (1005M) Capacitor)
pins: 1, 2

## GCM155R71H471KA37D
designator C?  Capacitance: 470pF  (hidden comment: *)
Capacitor, Ceramic (MLCC), 470pF, ±10%, 50V, X7R, ±10%, SMD 0402; Manufacturer: Murata Electronics; Manufacturer Part Number: GCM155R71H471KA37D
footprint CAP-0402 (0402 (1005M) Capacitor)
pins: 1, 2

## GCM155R71H472KA37D
designator C?  Capacitance: 4.7nF  (hidden comment: *)
Capacitor, Ceramic (MLCC), 4.7nF, ±10%, 50V, X7R, ±10%, SMD 0402; Manufacturer: Murata Electronics; Manufacturer Part Number: GCM155R71H472KA37D
footprint CAP-0402 (0402 (1005M) Capacitor)
pins: 1, 2

## GCM155R71H473KE02D
designator C?  Capacitance: 47nF  (hidden comment: *)
Capacitor, Ceramic (MLCC), 47nF, ±10%, 50V, X7R, ±10%, SMD 0402; Manufacturer: Murata Electronics; Manufacturer Part Number: GCM155R71H473KE02D
footprint CAP-0402 (0402 (1005M) Capacitor)
pins: 1, 2

## GCM155R71H473KE02J
designator C?  Capacitance: 47nF  (hidden comment: *)
Capacitor, Ceramic (MLCC), 47nF, ±10%, 50V, X7R, ±10%, SMD 0402; Manufacturer: Murata Electronics; Manufacturer Part Number: GCM155R71H473KE02J
footprint CAP-0402 (0402 (1005M) Capacitor)
pins: 1, 2

## GCM155R71H681KA37D
designator C?  Capacitance: 680pF  (hidden comment: *)
Capacitor, Ceramic (MLCC), 680pF, ±10%, 50V, X7R, ±10%, SMD 0402; Manufacturer: Murata Electronics; Manufacturer Part Number: GCM155R71H681KA37D
footprint CAP-0402 (0402 (1005M) Capacitor)
pins: 1, 2

## GCM155R71H682JA55D
designator C?  Capacitance: 6.8nF  (hidden comment: *)
Capacitor, Ceramic (MLCC), 6.8nF, ±5%, 50V, X7R, ±5%, SMD 0402; Manufacturer: Murata Electronics; Manufacturer Part Number: GCM155R71H682JA55D
footprint CAP-0402 (0402 (1005M) Capacitor)
pins: 1, 2

## GCM155R71H682KA55D
designator C?  Capacitance: 6.8nF  (hidden comment: *)
Capacitor, Ceramic (MLCC), 6.8nF, ±10%, 50V, X7R, ±10%, SMD 0402; Manufacturer: Murata Electronics; Manufacturer Part Number: GCM155R71H682KA55D
footprint CAP-0402 (0402 (1005M) Capacitor)
pins: 1, 2

## GCM155R71H683KE02D
designator C?  Capacitance: 68nF  (hidden comment: *)
Capacitor, Ceramic (MLCC), 68nF, ±10%, 50V, X7R, ±10%, SMD 0402; Manufacturer: Murata Electronics; Manufacturer Part Number: GCM155R71H683KE02D
footprint CAP-0402 (0402 (1005M) Capacitor)
pins: 1, 2

## GCM155R72A102KA37D
designator C?  Capacitance: 1nF  (hidden comment: *)
Capacitor, Ceramic (MLCC), 1nF, ±10%, 100V, X7R, ±10%, SMD 0402; Manufacturer: Murata Electronics; Manufacturer Part Number: GCM155R72A102KA37D
footprint CAP-0402 (0402 (1005M) Capacitor)
pins: 1, 2

## GCM155R72A221KA37D
designator C?  Capacitance: 220pF  (hidden comment: *)
Capacitor, Ceramic (MLCC), 220pF, ±10%, ±10%, SMD 0402; Manufacturer: Murata Electronics; Manufacturer Part Number: GCM155R72A221KA37D
footprint CAP-0402 (0402 (1005M) Capacitor)
pins: 1, 2

## GCM155R72A471KA37D
designator C?  Capacitance: 470pF  (hidden comment: *)
Capacitor, Ceramic (MLCC), 470pF, ±10%, 100V, X7R, ±10%, SMD 0402; Manufacturer: Murata Electronics; Manufacturer Part Number: GCM155R72A471KA37D
footprint CAP-0402 (0402 (1005M) Capacitor)
pins: 1, 2

## GCM1555C1H1R0BA16D
designator C?  Capacitance: 1pF  (hidden comment: *)
Capacitor, Ceramic (MLCC), 1pF, ±0.1pF, 50V, C0G, ±0.1pF, SMD 0402; Manufacturer: Murata Electronics; Manufacturer Part Number: GCM1555C1H1R0BA16D
footprint CAP-0402 (0402 (1005M) Capacitor)
pins: 1, 2

## GCM1555C1H1R0CA16D
designator C?  Capacitance: 1pF  (hidden comment: *)
Capacitor, Ceramic (MLCC), 1pF, ±0.25pF, 50V, C0G, ±0.25pF, SMD 0402; Manufacturer: Murata Electronics; Manufacturer Part Number: GCM1555C1H1R0CA16D
footprint CAP-0402 (0402 (1005M) Capacitor)
pins: 1, 2

## GCM1555C1H1R5BA16D
designator C?  Capacitance: 1.5pF  (hidden comment: *)
Capacitor, Ceramic (MLCC), 1.5pF, ±0.1pF, 50V, C0G, ±0.1pF, SMD 0402; Manufacturer: Murata Electronics; Manufacturer Part Number: GCM1555C1H1R5BA16D
footprint CAP-0402 (0402 (1005M) Capacitor)
pins: 1, 2

## GCM1555C1H1R5CA16D
designator C?  Capacitance: 1.5pF  (hidden comment: *)
Capacitor, Ceramic (MLCC), 1.5pF, ±0.25pF, 50V, C0G, ±0.25pF, SMD 0402; Manufacturer: Murata Electronics; Manufacturer Part Number: GCM1555C1H1R5CA16D
footprint CAP-0402 (0402 (1005M) Capacitor)
pins: 1, 2

## GCM1555C1H1R8CA16D
designator C?  Capacitance: 1.8pF  (hidden comment: *)
Capacitor, Ceramic (MLCC), 1.8pF, ±0.25pF, 50V, C0G, ±0.25pF, SMD 0402; Manufacturer: Murata Electronics; Manufacturer Part Number: GCM1555C1H1R8CA16D
footprint CAP-0402 (0402 (1005M) Capacitor)
pins: 1, 2

## GCM1555C1H2R2WA16D
designator C?  Capacitance: 2.2pF  (hidden comment: *)
Capacitor, Ceramic (MLCC), 2.2pF, ±0.05pF, 50V, C0G, ±0.05pF, SMD 0402; Manufacturer: Murata Electronics; Manufacturer Part Number: GCM1555C1H2R2WA16D
footprint CAP-0402 (0402 (1005M) Capacitor)
pins: 1, 2

## GCM1555C1H2R5CA16D
designator C?  Capacitance: 2.5pF  (hidden comment: *)
Capacitor, Ceramic (MLCC), 2.5pF, ±0.25pF, 50V, C0G, ±0.25pF, SMD 0402; Manufacturer: Murata Electronics; Manufacturer Part Number: GCM1555C1H2R5CA16D
footprint CAP-0402 (0402 (1005M) Capacitor)
pins: 1, 2

## GCM1555C1H3R0BA16D
designator C?  Capacitance: 3pF  (hidden comment: *)
Capacitor, Ceramic (MLCC), 3pF, ±0.1pF, 50V, C0G, ±0.1pF, SMD 0402; Manufacturer: Murata Electronics; Manufacturer Part Number: GCM1555C1H3R0BA16D
footprint CAP-0402 (0402 (1005M) Capacitor)
pins: 1, 2

## GCM1555C1H3R3BA16D
designator C?  Capacitance: 3.3pF  (hidden comment: *)
Capacitor, Ceramic (MLCC), 3.3pF, ±0.1pF, 50V, C0G, ±0.1pF, SMD 0402; Manufacturer: Murata Electronics; Manufacturer Part Number: GCM1555C1H3R3BA16D
footprint CAP-0402 (0402 (1005M) Capacitor)
pins: 1, 2

## GCM1555C1H3R6CA16D
designator C?  Capacitance: 3.6pF  (hidden comment: *)
Capacitor, Ceramic (MLCC), 3.6pF, ±0.25pF, 50V, C0G, ±0.25pF, SMD 0402; Manufacturer: Murata Electronics; Manufacturer Part Number: GCM1555C1H3R6CA16D
footprint CAP-0402 (0402 (1005M) Capacitor)
pins: 1, 2

## GCM1555C1H3R9BA16D
designator C?  Capacitance: 3.9pF  (hidden comment: *)
Capacitor, Ceramic (MLCC), 3.9pF, ±0.1pF, 50V, C0G, ±0.1pF, SMD 0402; Manufacturer: Murata Electronics; Manufacturer Part Number: GCM1555C1H3R9BA16D
footprint CAP-0402 (0402 (1005M) Capacitor)
pins: 1, 2

## GCM1555C1H3R9CA16D
designator C?  Capacitance: 3.9pF  (hidden comment: *)
Capacitor, Ceramic (MLCC), 3.9pF, ±0.25pF, 50V, C0G, ±0.25pF, SMD 0402; Manufacturer: Murata Electronics; Manufacturer Part Number: GCM1555C1H3R9CA16D
footprint CAP-0402 (0402 (1005M) Capacitor)
pins: 1, 2

## GCM1555C1H4R0CA16D
designator C?  Capacitance: 4pF  (hidden comment: *)
Capacitor, Ceramic (MLCC), 4pF, ±0.25pF, 50V, C0G, ±0.25pF, SMD 0402; Manufacturer: Murata Electronics; Manufacturer Part Number: GCM1555C1H4R0CA16D
footprint CAP-0402 (0402 (1005M) Capacitor)
pins: 1, 2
